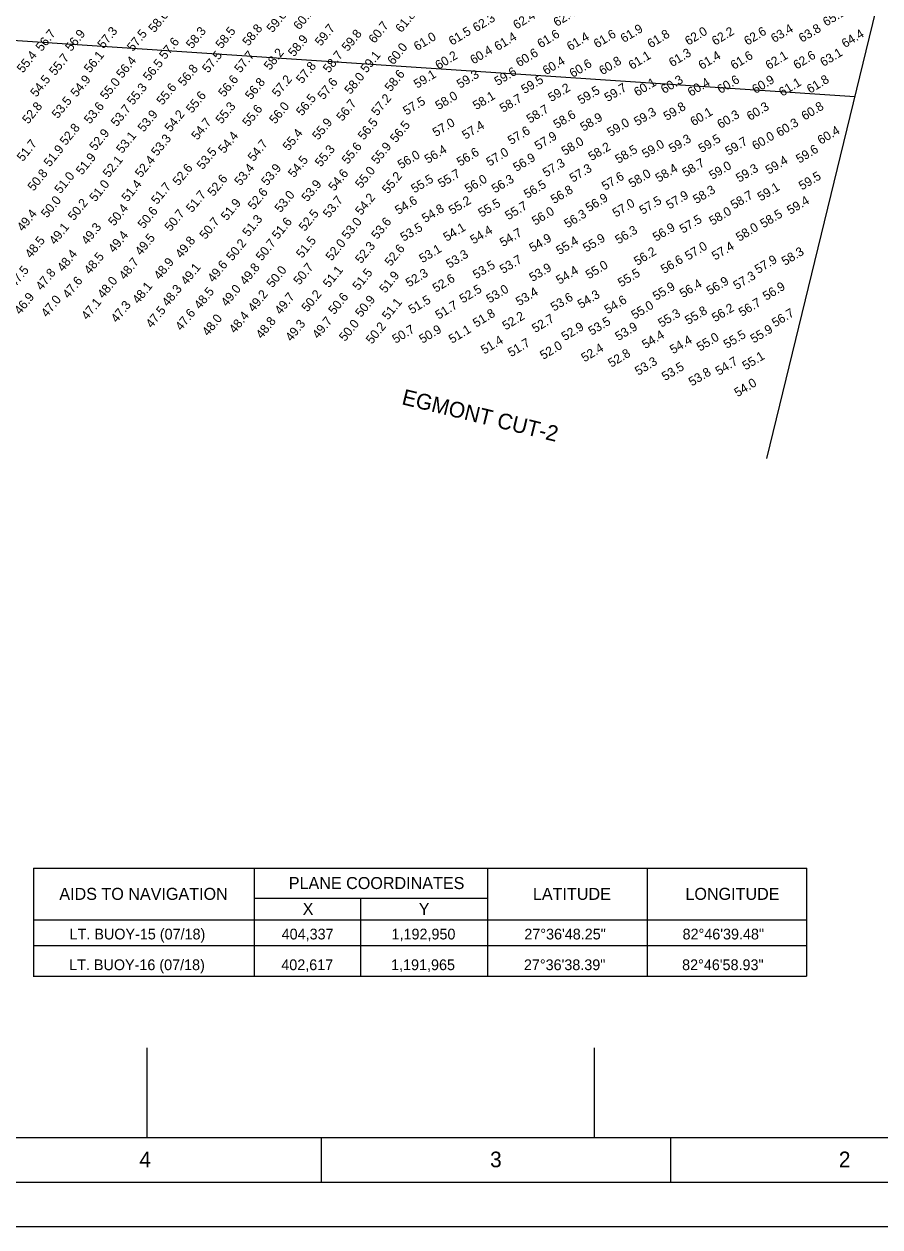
# Model space of a CAD drawing. Extents: x 401290 to 405690, y 1190598 to 1193998.
# Drawn here: x 403862 to 404819, y 1190598 to 1191942 of the extents above; entities that cross this region are included whole.
import ezdxf

# ---------------------------------------------------------------- set-up
doc = ezdxf.new("R2010")
doc.units = 0
for name, color, linetype in [('C-CHAN-WIDE', 7, 'Continuous'), ('G-ANNO-NPLT', 7, 'Continuous'), ('G-ANNO-TTLB', 7, 'Continuous'), ('V-ANNO-MATC', 7, 'Continuous'), ('V-ANNO-SCHD', 7, 'Continuous'), ('V-ANNO-SYMB', 7, 'Continuous'), ('V-CHAN-CNTR-IDEN', 7, 'Continuous'), ('V-TOPO-COOR-STAT', 7, 'Continuous'), ('V-TOPO-SOUN', 7, 'Continuous')]:
    doc.layers.add(name, color=color, linetype=linetype)

msp = doc.modelspace()

# ---------------------------------------------------------------- linework, layer by layer
at = {"layer": 'C-CHAN-WIDE'}
msp.add_line((402579.4, 1192009.5), (404790.9, 1191861.3), dxfattribs=at)
at = {"layer": 'G-ANNO-NPLT'}
msp.add_lwpolyline([(401290, 1193998.4), (405690, 1193998.4), (405690, 1190598.4), (401290, 1190598.4)], close=True, dxfattribs=at)
at = {"layer": 'G-ANNO-TTLB'}
for p, q in [((404195, 1190648.4), (404195, 1190698.4)), ((404585, 1190648.4), (404585, 1190698.4))]:
    msp.add_line(p, q, dxfattribs=at)
for points in [[(401340, 1190648.4), (405640, 1190648.4), (405640, 1193948.4), (401340, 1193948.4)], [(405590, 1193898.4), (401465, 1193898.4), (401465, 1190698.4), (405590, 1190698.4)]]:
    msp.add_lwpolyline(points, close=True, dxfattribs=at)
at = {"layer": 'V-ANNO-MATC'}
msp.add_line((404692.3, 1191457), (405077.8, 1193037.5), dxfattribs=at)
at = {"layer": 'V-ANNO-SCHD'}
for p, q in [((403873, 1190999.4), (404737, 1190999.4)), ((403873, 1190999.4), (403873, 1190878.6)), ((404119.6, 1190999.4), (404119.6, 1190878.6)), ((404380.4, 1190999.4), (404380.4, 1190878.6)), ((404558.7, 1190999.4), (404558.7, 1190878.6)), ((404737, 1190878.6), (404737, 1190999.4)), ((404119.6, 1190965.8), (404380.4, 1190965.8)), ((404238.5, 1190965.8), (404238.5, 1190878.6)), ((403873, 1190941.7), (404737, 1190941.7)), ((403873, 1190912.8), (404737, 1190912.8)), ((403872.5, 1190878.6), (404736.6, 1190878.6))]:
    msp.add_line(p, q, dxfattribs=at)
at = {"layer": 'V-TOPO-COOR-STAT'}
for p, q in [((404000, 1190698.4), (404000, 1190798.4)), ((404500, 1190698.4), (404500, 1190798.4))]:
    msp.add_line(p, q, dxfattribs=at)

# ---------------------------------------------------------------- texts
at = {"layer": 'G-ANNO-TTLB'}
for s, p in [('4', (403991.3, 1190665.1)), ('3', (404383.2, 1190665.1)), ('2', (404772.9, 1190665.1))]:
    msp.add_text(s, height=17.5, dxfattribs=at).set_placement(p)
at = {"layer": 'V-ANNO-SCHD'}
for s, height, p in [('PLANE COORDINATES', 13.471, (404158.3, 1190975.9)), ('AIDS TO NAVIGATION', 13.471, (403901.9, 1190963.8)), ('LATITUDE', 13.47, (404431.1, 1190963.8)), ('LONGITUDE', 13.47, (404601.5, 1190963.8)), ('X', 13.5, (404173.8, 1190947)), ('Y', 13.5, (404303.5, 1190947))]:
    msp.add_text(s, height=height, rotation=0.0001, dxfattribs=at).set_placement(p)
at = {"layer": 'V-ANNO-SYMB'}
for s, p in [('LT. BUOY-15 (07/18)', (403913.4, 1190919.6)), ('404,337', (404150.3, 1190919.6)), ('1,192,950', (404273.1, 1190919.6)), ('27%%D36\'48.25"', (404421.5, 1190919.6)), ('82%%D46\'39.48"', (404598.3, 1190919.6)), ('LT. BUOY-16 (07/18)', (403912.9, 1190885.3)), ('402,617', (404149.9, 1190885.3)), ('1,191,965', (404272.6, 1190885.3)), ('27%%D36\'38.39"', (404421, 1190885.3)), ('82%%D46\'58.93"', (404597.8, 1190885.3))]:
    msp.add_text(s, height=12, dxfattribs=at).set_placement(p)
at = {"layer": 'V-CHAN-CNTR-IDEN'}
msp.add_text('EGMONT CUT-2', height=17.52, rotation=346.2946, dxfattribs=at).set_placement((404283.6, 1191517.7))
at = {"layer": 'V-TOPO-SOUN'}
for s, rotation, p in [('58.6 ', 51.05, (404008.2, 1191932)), ('59.6 ', 51.05, (404140.2, 1191932)), ('60.1 ', 51.05, (404170.2, 1191935)), ('61.8 ', 51.05, (404284.2, 1191932)), ('62.3 ', 31.2939, (404367.7, 1191933)), ('62.4 ', 31.2939, (404412.7, 1191936)), ('62.4 ', 31.2939, (404457.7, 1191939)), ('65.1 ', 31.2939, (404758.8, 1191939.3)), ('57.3 ', 51.05, (403951.2, 1191914)), ('58.3 ', 51.05, (404050.2, 1191914)), ('58.5 ', 51.05, (404083.2, 1191914)), ('58.8 ', 51.05, (404113.2, 1191917)), ('59.7 ', 51.05, (404194.2, 1191917)), ('60.7 ', 51.05, (404254.2, 1191920)), ('61.5 ', 31.2939, (404340.7, 1191918)), ('61.9 ', 31.2939, (404532.7, 1191921)), ('62.0 ', 31.2939, (404604.7, 1191918)), ('62.2 ', 31.2939, (404634.7, 1191918)), ('62.6 ', 31.2939, (404670.7, 1191918)), ('63.4 ', 31.2939, (404700.7, 1191921)), ('63.8 ', 31.2939, (404731.8, 1191921.3)), ('56.7 ', 51.05, (403882.2, 1191911)), ('56.9 ', 51.05, (403915.2, 1191911)), ('57.5 ', 51.05, (403984.2, 1191911)), ('57.6 ', 51.05, (404020.2, 1191902)), ('58.9 ', 51.05, (404164.2, 1191905)), ('59.8 ', 51.05, (404224.2, 1191911)), ('61.0 ', 31.2939, (404301.7, 1191912)), ('61.4 ', 31.2939, (404391.7, 1191912)), ('61.6 ', 31.2939, (404439.7, 1191915)), ('61.4 ', 31.2939, (404472.7, 1191912)), ('61.6 ', 31.2939, (404502.7, 1191915)), ('61.8 ', 31.2939, (404562.7, 1191915)), ('64.4 ', 31.2939, (404779.8, 1191915.3)), ('55.4 ', 51.05, (403861.2, 1191887)), ('56.1 ', 51.05, (403936.2, 1191887)), ('57.5 ', 51.05, (404068.2, 1191887)), ('57.7 ', 51.05, (404104.2, 1191887)), ('58.2 ', 51.05, (404137.2, 1191890)), ('58.7 ', 51.05, (404203.2, 1191887)), ('59.1 ', 51.05, (404245.2, 1191887)), ('60.0 ', 51.05, (404275.2, 1191896)), ('60.2 ', 31.2939, (404325.7, 1191891)), ('60.4 ', 31.2939, (404364.7, 1191897)), ('60.6 ', 31.2939, (404415.7, 1191894)), ('61.1 ', 31.2939, (404541.7, 1191891)), ('61.3 ', 31.2939, (404586.7, 1191894)), ('61.4 ', 31.2939, (404619.7, 1191891)), ('61.6 ', 31.2939, (404655.7, 1191891)), ('62.1 ', 31.2939, (404694.7, 1191891)), ('62.6 ', 31.2939, (404725.8, 1191891.3)), ('63.1 ', 31.2939, (404755.8, 1191894.3)), ('55.7 ', 51.05, (403897.2, 1191884)), ('56.4 ', 51.05, (403972.2, 1191881)), ('56.5 ', 51.05, (404002.2, 1191878)), ('56.8 ', 51.05, (404041.2, 1191872)), ('57.8 ', 51.05, (404173.2, 1191875)), ('60.4 ', 31.2939, (404445.7, 1191885)), ('60.6 ', 31.2939, (404475.7, 1191882)), ('60.8 ', 31.2939, (404508.7, 1191885)), ('54.5 ', 51.05, (403876.2, 1191860)), ('54.9 ', 51.05, (403921.2, 1191860)), ('56.6 ', 51.05, (404086.2, 1191860)), ('57.2 ', 51.05, (404146.2, 1191860)), ('58.0 ', 51.05, (404227.2, 1191863)), ('58.6 ', 51.05, (404272.2, 1191866)), ('59.1 ', 31.2939, (404301.7, 1191870)), ('59.3 ', 31.2939, (404349.7, 1191870)), ('59.6 ', 31.2939, (404391.7, 1191873)), ('59.5 ', 31.2939, (404421.7, 1191864)), ('60.3 ', 31.2939, (404577.7, 1191864)), ('60.6 ', 31.2939, (404640.7, 1191864)), ('60.9 ', 31.2939, (404679.7, 1191864)), ('61.8 ', 31.2939, (404740.8, 1191864.3)), ('55.0 ', 51.05, (403954.2, 1191857)), ('55.3 ', 51.05, (403984.2, 1191851)), ('55.6 ', 51.05, (404017.2, 1191851)), ('56.8 ', 51.05, (404116.2, 1191857)), ('57.6 ', 51.05, (404197.2, 1191857)), ('59.2 ', 31.2939, (404451.7, 1191855)), ('59.5 ', 31.2939, (404484.7, 1191852)), ('59.7 ', 31.2939, (404514.7, 1191855)), ('60.1 ', 31.2939, (404547.7, 1191861)), ('60.4 ', 31.2939, (404607.7, 1191861)), ('61.1 ', 31.2939, (404709.7, 1191861)), ('53.5 ', 51.05, (403900.2, 1191836)), ('55.6 ', 51.05, (404050.2, 1191842)), ('56.5 ', 51.05, (404173.2, 1191839)), ('56.7 ', 51.05, (404218.2, 1191833)), ('57.2 ', 51.05, (404257.2, 1191839)), ('57.5 ', 31.2939, (404289.7, 1191840)), ('58.0 ', 31.2939, (404325.7, 1191846)), ('58.1 ', 31.2939, (404367.7, 1191846)), ('58.7 ', 31.2939, (404397.7, 1191843)), ('52.8 ', 51.05, (403867.2, 1191830)), ('53.6 ', 51.05, (403936.2, 1191830)), ('53.7 ', 51.05, (403966.2, 1191827)), ('53.9 ', 51.05, (403996.2, 1191821)), ('54.2 ', 51.05, (404026.2, 1191821)), ('55.3 ', 51.05, (404083.2, 1191830)), ('55.6 ', 51.05, (404113.2, 1191827)), ('56.0 ', 51.05, (404143.2, 1191830)), ('58.7 ', 31.2939, (404427.7, 1191831)), ('58.6 ', 31.2939, (404457.7, 1191825)), ('59.3 ', 31.2939, (404547.7, 1191828)), ('59.8 ', 31.2939, (404580.7, 1191834)), ('60.1 ', 31.2939, (404610.7, 1191828)), ('60.3 ', 31.2939, (404640.7, 1191825)), ('60.3 ', 31.2939, (404673.7, 1191834)), ('60.8 ', 31.2939, (404734.8, 1191834.3)), ('52.8 ', 51.05, (403909.2, 1191806)), ('54.7 ', 51.05, (404056.2, 1191812)), ('55.9 ', 51.05, (404191.2, 1191812)), ('56.5 ', 51.05, (404242.2, 1191812)), ('56.5 ', 51.05, (404278.2, 1191809)), ('57.0 ', 31.2939, (404322.7, 1191816)), ('57.4 ', 31.2939, (404355.7, 1191813)), ('58.9 ', 31.2939, (404487.7, 1191822)), ('59.0 ', 31.2939, (404517.7, 1191816)), ('60.3 ', 31.2939, (404706.7, 1191816)), ('52.9 ', 51.05, (403942.2, 1191800)), ('53.1 ', 51.05, (403972.2, 1191797)), ('53.3 ', 51.05, (404011.2, 1191794)), ('54.4 ', 51.05, (404086.2, 1191797)), ('55.4 ', 51.05, (404158.2, 1191800)), ('57.6 ', 31.2939, (404406.7, 1191807)), ('57.9 ', 31.2939, (404436.7, 1191801)), ('59.3 ', 31.2939, (404586.7, 1191798)), ('59.5 ', 31.2939, (404619.7, 1191798)), ('59.7 ', 31.2939, (404649.7, 1191795)), ('60.0 ', 31.2939, (404679.7, 1191801)), ('60.4 ', 31.2939, (404752.8, 1191807.3)), ('51.7 ', 51.05, (403861.2, 1191788)), ('51.9 ', 51.05, (403891.2, 1191782)), ('53.5 ', 51.05, (404062.2, 1191779)), ('54.7 ', 51.05, (404119.2, 1191788)), ('55.3 ', 51.05, (404194.2, 1191782)), ('55.6 ', 51.05, (404224.2, 1191785)), ('55.9 ', 51.05, (404257.2, 1191785)), ('56.4 ', 31.2939, (404313.7, 1191786)), ('56.6 ', 31.2939, (404349.7, 1191783)), ('57.0 ', 31.2939, (404382.7, 1191783)), ('58.0 ', 31.2939, (404466.7, 1191795)), ('58.2 ', 31.2939, (404496.7, 1191789)), ('58.5 ', 31.2939, (404526.7, 1191786)), ('59.0 ', 31.2939, (404556.7, 1191792)), ('59.6 ', 31.2939, (404728.8, 1191786.3)), ('51.9 ', 51.05, (403927.2, 1191773)), ('52.1 ', 51.05, (403957.2, 1191770)), ('52.4 ', 51.05, (403993.2, 1191770)), ('54.5 ', 51.05, (404164.2, 1191770)), ('56.0 ', 31.2939, (404283.7, 1191780)), ('56.9 ', 31.2939, (404412.7, 1191777)), ('57.3 ', 31.2939, (404445.7, 1191771)), ('58.7 ', 31.2939, (404601.7, 1191771)), ('59.4 ', 31.2939, (404694.7, 1191774)), ('50.8 ', 51.05, (403873.2, 1191755)), ('51.0 ', 51.05, (403903.2, 1191752)), ('52.6 ', 51.05, (404035.2, 1191761)), ('53.4 ', 51.05, (404104.2, 1191761)), ('53.9 ', 51.05, (404134.2, 1191761)), ('54.6 ', 51.05, (404209.2, 1191755)), ('55.0 ', 51.05, (404239.2, 1191758)), ('55.2 ', 51.05, (404269.2, 1191752)), ('55.7 ', 31.2939, (404328.7, 1191759)), ('57.3 ', 31.2939, (404475.7, 1191765)), ('57.6 ', 31.2939, (404511.7, 1191756)), ('58.0 ', 31.2939, (404541.7, 1191759)), ('58.4 ', 31.2939, (404571.7, 1191765)), ('59.0 ', 31.2939, (404631.7, 1191768)), ('59.3 ', 31.2939, (404661.7, 1191765)), ('59.5 ', 31.2939, (404731.8, 1191756.3)), ('51.0 ', 51.05, (403942.2, 1191743)), ('51.4 ', 51.05, (403978.2, 1191743)), ('51.7 ', 51.05, (404011.2, 1191740)), ('52.6 ', 51.05, (404074.2, 1191749)), ('53.9 ', 51.05, (404179.2, 1191743)), ('55.5 ', 31.2939, (404298.7, 1191753)), ('56.0 ', 31.2939, (404358.7, 1191753)), ('56.3 ', 31.2939, (404388.7, 1191753)), ('56.5 ', 31.2939, (404424.7, 1191747)), ('59.1 ', 31.2939, (404685.7, 1191744)), ('50.0 ', 51.05, (403888.2, 1191725)), ('51.7 ', 51.05, (404050.2, 1191731)), ('52.6 ', 51.05, (404119.2, 1191734)), ('53.0 ', 51.05, (404149.2, 1191731)), ('53.7 ', 51.05, (404203.2, 1191725)), ('54.2 ', 51.05, (404239.2, 1191728)), ('54.6 ', 31.2939, (404280.7, 1191729)), ('55.2 ', 31.2939, (404340.7, 1191729)), ('56.8 ', 31.2939, (404454.7, 1191741)), ('56.9 ', 31.2939, (404493.7, 1191732)), ('57.5 ', 31.2939, (404553.7, 1191729)), ('57.9 ', 31.2939, (404583.7, 1191735)), ('58.3 ', 31.2939, (404613.7, 1191741)), ('58.7 ', 31.2939, (404655.7, 1191735)), ('59.4 ', 31.2939, (404718.7, 1191729)), ('50.2 ', 51.05, (403918.2, 1191722)), ('50.4 ', 51.05, (403963.2, 1191716)), ('50.6 ', 51.05, (403996.2, 1191713)), ('50.7 ', 51.05, (404026.2, 1191710)), ('51.9 ', 51.05, (404089.2, 1191722)), ('52.5 ', 51.05, (404176.2, 1191710)), ('54.8 ', 31.2939, (404310.7, 1191720)), ('55.5 ', 31.2939, (404373.7, 1191726)), ('55.7 ', 31.2939, (404403.7, 1191723)), ('56.0 ', 31.2939, (404433.7, 1191717)), ('57.0 ', 31.2939, (404523.7, 1191726)), ('58.0 ', 31.2939, (404631.7, 1191717)), ('49.4 ', 51.05, (403861.2, 1191710)), ('50.7 ', 51.05, (404065.2, 1191701)), ('51.3 ', 51.05, (404113.2, 1191704)), ('51.6 ', 51.05, (404146.2, 1191701)), ('53.0 ', 51.05, (404224.2, 1191701)), ('53.6 ', 51.05, (404257.2, 1191701)), ('56.3 ', 31.2939, (404469.7, 1191714)), ('57.5 ', 31.2939, (404598.7, 1191708)), ('58.5 ', 31.2939, (404688.7, 1191714)), ('49.1 ', 51.05, (403897.2, 1191695)), ('49.3 ', 51.05, (403933.2, 1191695)), ('49.4 ', 51.05, (403963.2, 1191686)), ('53.5 ', 31.2939, (404286.7, 1191699)), ('54.1 ', 31.2939, (404334.7, 1191699)), ('54.4 ', 31.2939, (404364.7, 1191696)), ('54.7 ', 31.2939, (404397.7, 1191693)), ('56.3 ', 31.2939, (404526.7, 1191696)), ('56.9 ', 31.2939, (404568.7, 1191699)), ('58.0 ', 31.2939, (404661.7, 1191699)), ('48.5 ', 51.05, (403870.2, 1191680)), ('49.5 ', 51.05, (403993.2, 1191683)), ('49.8 ', 51.05, (404038.2, 1191680)), ('50.2 ', 51.05, (404095.2, 1191677)), ('50.7 ', 51.05, (404128.2, 1191677)), ('51.5 ', 51.05, (404173.2, 1191680)), ('52.0 ', 51.05, (404206.2, 1191677)), ('52.3 ', 51.05, (404239.2, 1191674)), ('52.6 ', 51.05, (404272.2, 1191671)), ('53.1 ', 31.2939, (404307.7, 1191675)), ('54.9 ', 31.2939, (404430.7, 1191687)), ('55.4 ', 31.2939, (404460.7, 1191684)), ('55.9 ', 31.2939, (404490.7, 1191687)), ('57.0 ', 31.2939, (404604.7, 1191678)), ('57.4 ', 31.2939, (404634.7, 1191678)), ('48.4 ', 51.05, (403906.2, 1191665)), ('48.5 ', 51.05, (403936.2, 1191662)), ('48.7 ', 51.05, (403975.2, 1191656)), ('53.3 ', 31.2939, (404337.7, 1191669)), ('53.7 ', 31.2939, (404397.7, 1191663)), ('56.2 ', 31.2939, (404547.7, 1191672)), ('56.6 ', 31.2939, (404577.7, 1191663)), ('57.9 ', 31.2939, (404682.7, 1191663)), ('58.3 ', 31.2939, (404712.7, 1191672)), ('47.5 ', 51.05, (403852.2, 1191647)), ('47.8 ', 51.05, (403882.2, 1191644)), ('48.9 ', 51.05, (404014.2, 1191656)), ('49.1 ', 51.05, (404044.2, 1191650)), ('49.6 ', 51.05, (404074.2, 1191653)), ('49.8 ', 51.05, (404110.2, 1191650)), ('50.0 ', 51.05, (404140.2, 1191647)), ('50.7 ', 51.05, (404170.2, 1191650)), ('51.1 ', 51.05, (404203.2, 1191647)), ('51.5 ', 51.05, (404236.2, 1191644)), ('52.3 ', 31.2939, (404292.7, 1191648)), ('53.5 ', 31.2939, (404367.7, 1191657)), ('53.9 ', 31.2939, (404430.7, 1191654)), ('54.4 ', 31.2939, (404460.7, 1191651)), ('55.0 ', 31.2939, (404493.7, 1191657)), ('55.5 ', 31.2939, (404529.7, 1191648)), ('47.6 ', 51.05, (403912.2, 1191635)), ('48.0 ', 51.05, (403951.2, 1191635)), ('51.9 ', 51.05, (404266.2, 1191641)), ('52.6 ', 31.2939, (404322.7, 1191642)), ('56.4 ', 31.2939, (404598.7, 1191636)), ('56.9 ', 31.2939, (404628.7, 1191639)), ('57.3 ', 31.2939, (404658.7, 1191645)), ('46.9 ', 51.05, (403858.2, 1191617)), ('48.1 ', 51.05, (403990.2, 1191629)), ('48.3 ', 51.05, (404023.2, 1191626)), ('48.5 ', 51.05, (404059.2, 1191623)), ('49.0 ', 51.05, (404089.2, 1191626)), ('49.2 ', 51.05, (404119.2, 1191620)), ('49.7 ', 51.05, (404149.2, 1191617)), ('50.2 ', 51.05, (404179.2, 1191620)), ('50.6 ', 51.05, (404209.2, 1191617)), ('52.5 ', 31.2939, (404352.7, 1191630)), ('53.0 ', 31.2939, (404382.7, 1191630)), ('53.4 ', 31.2939, (404415.7, 1191627)), ('53.6 ', 31.2939, (404454.7, 1191621)), ('54.3 ', 31.2939, (404484.7, 1191624)), ('55.9 ', 31.2939, (404568.7, 1191633)), ('56.9 ', 31.2939, (404691.7, 1191633)), ('47.0 ', 51.05, (403888.2, 1191614)), ('47.1 ', 51.05, (403933.2, 1191611)), ('47.3 ', 51.05, (403966.2, 1191608)), ('50.9 ', 51.05, (404239.2, 1191614)), ('51.1 ', 51.05, (404269.2, 1191611)), ('51.5 ', 31.2939, (404295.7, 1191618)), ('51.7 ', 31.2939, (404325.7, 1191612)), ('54.6 ', 31.2939, (404514.7, 1191618)), ('55.0 ', 31.2939, (404544.7, 1191612)), ('56.2 ', 31.2939, (404634.7, 1191609)), ('56.7 ', 31.2939, (404664.7, 1191615)), ('47.5 ', 51.05, (404005.2, 1191602)), ('47.6 ', 51.05, (404038.2, 1191599)), ('48.0 ', 51.05, (404068.2, 1191593)), ('48.4 ', 51.05, (404098.2, 1191596)), ('48.8 ', 51.05, (404128.2, 1191590)), ('49.7 ', 51.05, (404191.2, 1191590)), ('51.8 ', 31.2939, (404367.7, 1191603)), ('52.2 ', 31.2939, (404400.7, 1191600)), ('52.7 ', 31.2939, (404433.7, 1191597)), ('53.5 ', 31.2939, (404496.7, 1191594)), ('55.3 ', 31.2939, (404574.7, 1191603)), ('55.8 ', 31.2939, (404604.7, 1191606)), ('56.7 ', 31.2939, (404701.8, 1191603.3)), ('49.3 ', 51.05, (404161.2, 1191587)), ('50.0 ', 51.05, (404221.2, 1191587)), ('50.2 ', 51.05, (404251.2, 1191584)), ('50.7 ', 31.2939, (404277.7, 1191585)), ('50.9 ', 31.2939, (404307.7, 1191585)), ('51.1 ', 31.2939, (404340.7, 1191585)), ('52.9 ', 31.2939, (404466.7, 1191588)), ('53.9 ', 31.2939, (404526.7, 1191588)), ('55.9 ', 31.2939, (404677.8, 1191585.3)), ('51.4 ', 31.2939, (404376.7, 1191573)), ('51.7 ', 31.2939, (404406.7, 1191570)), ('52.0 ', 31.2939, (404442.7, 1191567)), ('54.4 ', 31.2939, (404556.7, 1191579)), ('54.4 ', 31.2939, (404587.8, 1191573.3)), ('55.0 ', 31.2939, (404617.8, 1191576.3)), ('55.5 ', 31.2939, (404647.8, 1191579.3)), ('52.4 ', 31.2939, (404488.8, 1191564.3)), ('52.8 ', 31.2939, (404518.8, 1191558.3)), ('55.1 ', 31.2939, (404668.8, 1191555.3)), ('53.3 ', 31.2939, (404548.8, 1191549.3)), ('53.5 ', 31.2939, (404578.8, 1191543.3)), ('54.7 ', 31.2939, (404638.8, 1191549.3)), ('53.8 ', 31.2939, (404608.8, 1191537.3)), ('54.0 ', 31.2939, (404659.8, 1191525.3))]:
    msp.add_text(s, height=10, rotation=rotation, dxfattribs=at).set_placement(p)

doc.saveas('drawing.dxf')
